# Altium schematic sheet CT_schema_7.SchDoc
size 370 x 335 mm
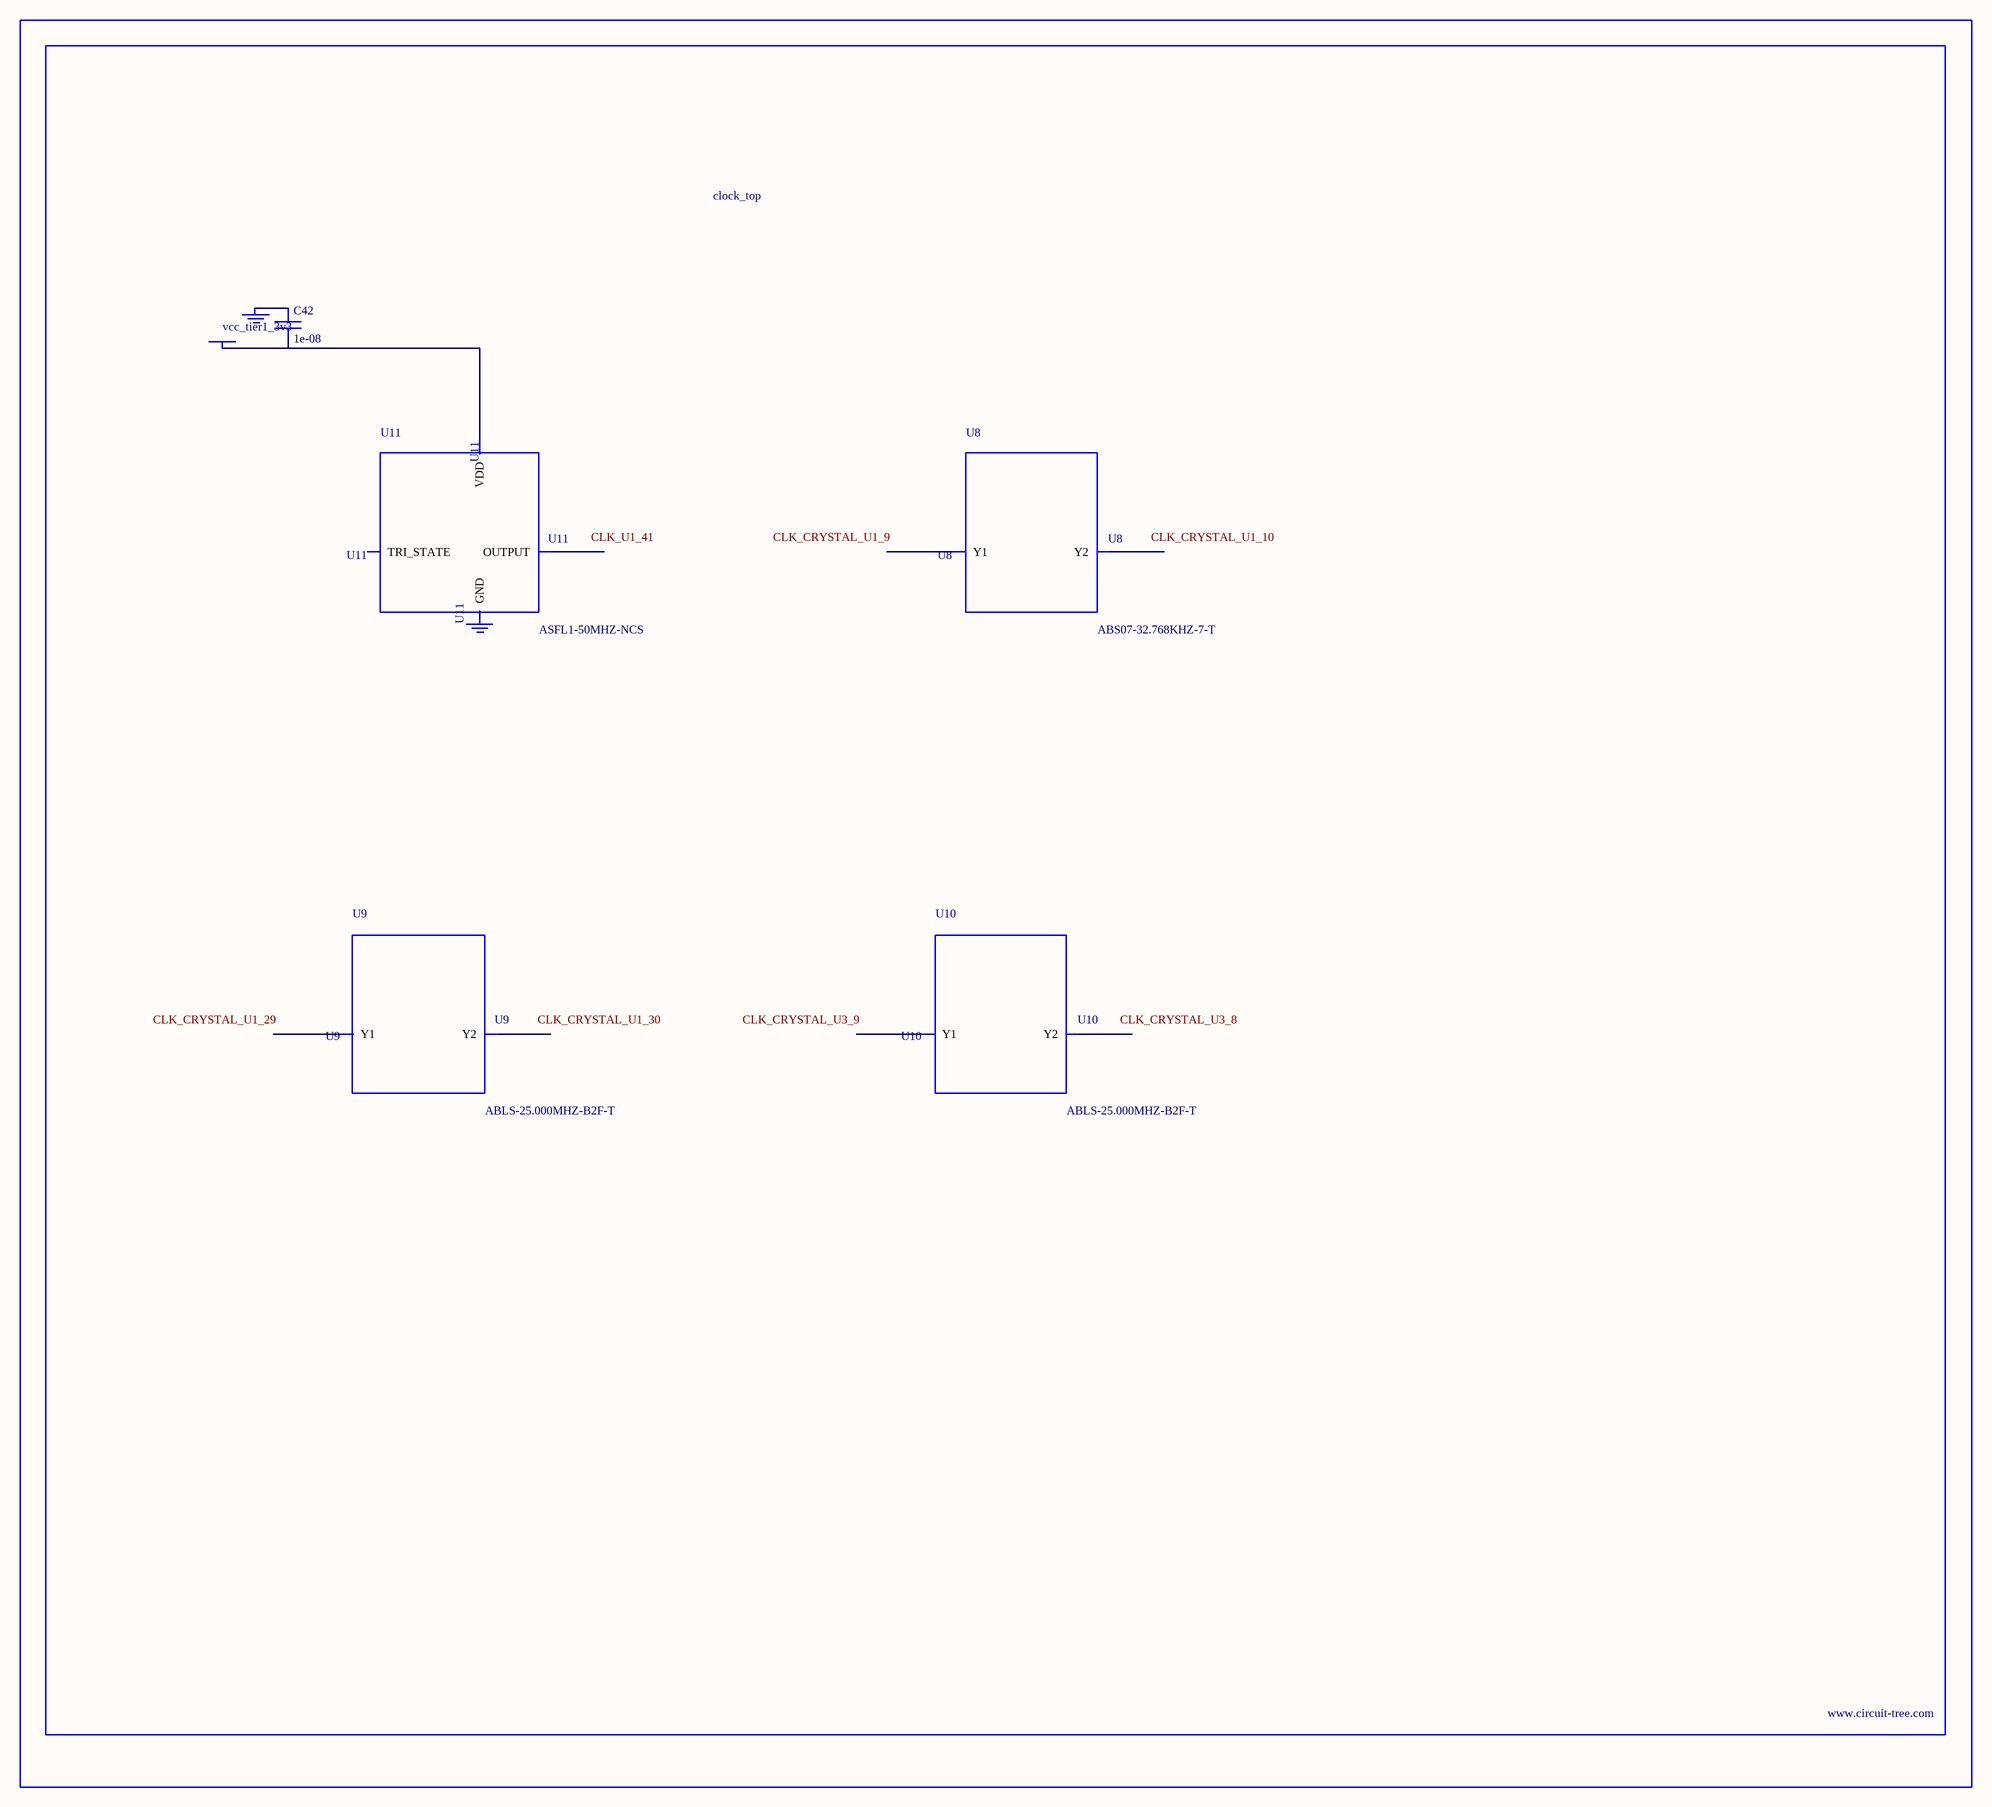
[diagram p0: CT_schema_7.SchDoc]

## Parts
BORDER6  (no value)
C42  1e-08  [C0402]
GND_INSTANCE_6_0  (no value)
GND_INSTANCE_6_1  (no value)
POWER_INSTANCE_6_0  vcc_tier1_3v3
U8  ABS07-32.768KHZ-7-T  [ABS07-32.768KHZ-7-T]
U9  ABLS-25.000MHZ-B2F-T  [ABLS-25.000MHZ-B2F-T]
U10  ABLS-25.000MHZ-B2F-T  [ABLS-25.000MHZ-B2F-T]
U11  ASFL1-50MHZ-NCS  [ASFL1]

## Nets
NetC42_1: C42.1 GND_INSTANCE_6_0.0(GND)
NetC42_2: C42.2 POWER_INSTANCE_6_0.0(PWR) U11.4(VDD)

Not connected (* = marked no-connect by the designer): GND_INSTANCE_6_1 0(GND); U8 1(Y1) 2(Y2); U9 1(Y1) 2(Y2); U10 1(Y1) 2(Y2); U11 1(TRI_STATE) 2(GND) 3(OUTPUT)

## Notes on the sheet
- Labels drawn without touching a wire or pin: CLK_CRYSTAL_U1_9, CLK_CRYSTAL_U1_10, CLK_CRYSTAL_U1_29, CLK_CRYSTAL_U1_30, CLK_CRYSTAL_U3_8, CLK_CRYSTAL_U3_9, CLK_U1_41

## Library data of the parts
BORDER6 = BORDER_PAGE6
C42 = C0402C103K3RAC
GND_INSTANCE_6_0 GND_INSTANCE_6_1 = GND
POWER_INSTANCE_6_0 = PWR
